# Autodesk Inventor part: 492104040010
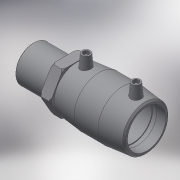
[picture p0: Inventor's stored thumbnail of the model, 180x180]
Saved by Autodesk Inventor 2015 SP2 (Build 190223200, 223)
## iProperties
Created: 2017-06
Part Number: 492104040010
Material: Generic
Description: PLASSON Male Transition Coupler 40 x 1"
Document SubType Name: Modeling
Designer: KIM
Mass: 155.96 g
Surface Area: 430.23 cm^2
Volume: 155.96 cm^3
Density: 1 g/cm^3
Appearance: Default
Author: KIM
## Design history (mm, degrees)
derived "492104.ipt"
feature "Solid1::492104.ipt"
tag "TaggingFeature1"
body "Solid1"
other parameters: "d0" = 97, "d2" = 56, "d3" = 47, "d4" = 32.33333, "d5" = 50.4, "d6" = 38, "d8" = 168 deg, "d10" = 18.8, "d11" = 6.26667, "d29" = 46, "d30" = 14, "d31" = 33.95, "d34" = 5 deg, "d41" = 4, "d42" = 14, "d43" = 0, "d48" = 3, "d49" = 0, "d57" = 29, "d58" = 33.249, "d59" = 26.5992, "d60" = 30.6, "d61" = 56, "d62" = 0.66498, "d65" = 1.68, "d70" = 0.1, "d71" = 34, "d72" = 8.5, "d73" = 18.8, "d75" = 0, "L_" = 131, "L_1" = 47, "D_1" = 56, "A_" = 46, "d_2" = 12, "L_2" = 34, "D_" = 29, "R_" = 33.249
